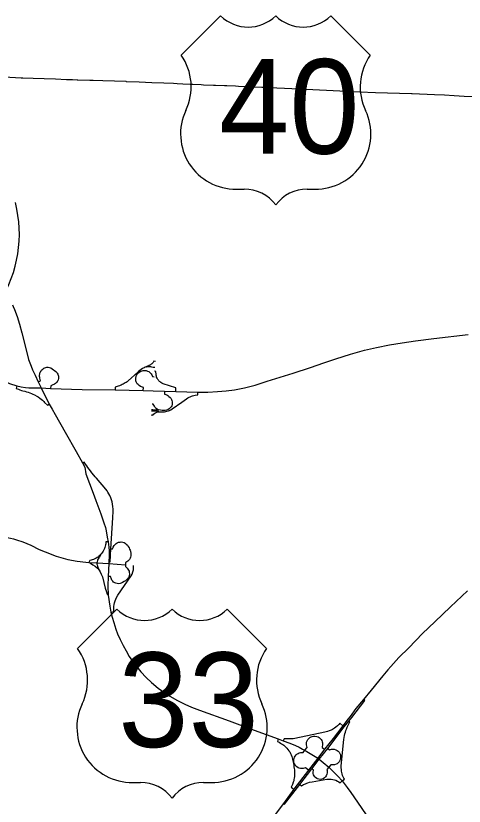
# Model space of a CAD drawing. Extents: x -7.1 to 34, y 0 to 22.
# Drawn here: x 6.584 to 7.196, y 16.034 to 17.111 of the extents above; entities that cross this region are included whole.
import ezdxf

# ---------------------------------------------------------------- set-up
doc = ezdxf.new("R2010")
doc.units = 0
for name, color, linetype in [('GM_X_Interchange_Ramps', 7, 'Continuous'), ('GM_X_Interstate_Route', 7, 'Continuous'), ('GM_X_Interstate_Shield', 7, 'Continuous'), ('GM_X_State_Route', 7, 'Continuous'), ('GM_X_US_Route', 7, 'Continuous'), ('GM_X_US_Shield', 7, 'Continuous')]:
    doc.layers.add(name, color=color, linetype=linetype)

msp = doc.modelspace()

# ---------------------------------------------------------------- linework, layer by layer
at = {"layer": 'GM_X_Interchange_Ramps'}
for points in [[(6.7745, 16.6397), (6.7724, 16.6399), (6.7713, 16.6384), (6.7705, 16.6375), (6.7696, 16.6366), (6.7689, 16.636), (6.768, 16.6353), (6.7669, 16.6346), (6.7659, 16.6341), (6.7647, 16.6335), (6.7637, 16.6332), (6.762, 16.6325), (6.7605, 16.6319), (6.759, 16.6311), (6.757, 16.63), (6.755, 16.6288), (6.7532, 16.6275), (6.7514, 16.626), (6.7504, 16.6253), (6.7372, 16.6131), (6.7358, 16.6121), (6.7345, 16.6112), (6.7333, 16.6104), (6.7319, 16.6095), (6.7303, 16.6087), (6.7291, 16.6081), (6.7279, 16.6076), (6.7263, 16.607), (6.7253, 16.6066), (6.7237, 16.6062), (6.7197, 16.6048), (6.7196, 16.6009)], [(6.6146, 16.612), (6.6178, 16.6134), (6.6169, 16.617), (6.6167, 16.618), (6.6165, 16.6193), (6.6165, 16.6202), (6.6165, 16.6213), (6.6167, 16.6225), (6.617, 16.6237), (6.6175, 16.625), (6.6181, 16.6261), (6.6188, 16.6272), (6.6198, 16.6284), (6.6211, 16.6294), (6.6225, 16.6304), (6.6237, 16.6309), (6.625, 16.6314), (6.6265, 16.6317), (6.6282, 16.6317), (6.63, 16.6316), (6.6318, 16.6311), (6.6338, 16.6295), (6.6389, 16.6259), (6.64, 16.6247), (6.6406, 16.6239), (6.6414, 16.6223), (6.6418, 16.6212), (6.6422, 16.6195), (6.6423, 16.6181), (6.6422, 16.6166), (6.6418, 16.6148), (6.6412, 16.6134), (6.6407, 16.6123), (6.6399, 16.6112), (6.6392, 16.6105), (6.6383, 16.6097), (6.637, 16.6088), (6.636, 16.6082), (6.6346, 16.6077), (6.6318, 16.6067), (6.6313, 16.6027)], [(6.758, 16.5999), (6.7581, 16.6042), (6.7556, 16.6051), (6.7541, 16.6058), (6.7522, 16.6069), (6.7508, 16.6081), (6.7497, 16.6094), (6.7489, 16.6109), (6.7484, 16.6121), (6.748, 16.6135), (6.7478, 16.6148), (6.7478, 16.6169), (6.7482, 16.6192), (6.7489, 16.6208), (6.7497, 16.6223), (6.7505, 16.6233), (6.7519, 16.6248), (6.7532, 16.6257), (6.7547, 16.6265), (6.7563, 16.6271), (6.7576, 16.6274), (6.7587, 16.6275), (6.7601, 16.6275), (6.762, 16.6273), (6.7639, 16.6266), (6.7653, 16.6259), (6.7666, 16.625), (6.768, 16.6238), (6.7688, 16.6228), (6.7695, 16.6216), (6.7707, 16.6191), (6.7727, 16.6189)], [(6.7738, 16.6314), (6.7715, 16.6316), (6.7697, 16.632), (6.7681, 16.6323), (6.7668, 16.6324), (6.7656, 16.6324), (6.7645, 16.6324), (6.7632, 16.6323), (6.7622, 16.6321), (6.762, 16.6325)], [(6.8022, 16.5986), (6.8023, 16.6039), (6.785, 16.6092), (6.7842, 16.6097), (6.7832, 16.6102), (6.7819, 16.611), (6.7808, 16.6118), (6.78, 16.6126), (6.7792, 16.6134), (6.7785, 16.6143), (6.7779, 16.6151), (6.7773, 16.6161), (6.7768, 16.6171), (6.7762, 16.6185), (6.7758, 16.6198), (6.7755, 16.621), (6.7754, 16.6219), (6.775, 16.6261), (6.7733, 16.6263)], [(6.5854, 16.6065), (6.5845, 16.603), (6.5877, 16.6018), (6.5897, 16.601), (6.5917, 16.6003), (6.5936, 16.5998), (6.5964, 16.5991), (6.5985, 16.5985), (6.6009, 16.5978), (6.6031, 16.597), (6.6056, 16.596), (6.6074, 16.5952), (6.6096, 16.5941), (6.6126, 16.5925), (6.6146, 16.5913), (6.6168, 16.5898), (6.6188, 16.5885), (6.6206, 16.5869), (6.6223, 16.5852), (6.6234, 16.5838), (6.6271, 16.5802), (6.6297, 16.5817)], [(6.7687, 16.5668), (6.771, 16.5665), (6.7721, 16.5678), (6.7738, 16.5692), (6.7747, 16.5698), (6.7765, 16.5706), (6.7778, 16.5709), (6.7784, 16.571), (6.7798, 16.5711), (6.7852, 16.5709), (6.7871, 16.5712), (6.7889, 16.5715), (6.7902, 16.5718), (6.7922, 16.5725), (6.7936, 16.573), (6.7955, 16.5739), (6.7973, 16.575), (6.8105, 16.5844), (6.8169, 16.5887), (6.8187, 16.5899), (6.8206, 16.5909), (6.8221, 16.5916), (6.8236, 16.5922), (6.8253, 16.5928), (6.827, 16.5933), (6.8285, 16.5936), (6.8325, 16.5943), (6.8325, 16.598)], [(6.787, 16.5991), (6.7869, 16.5951), (6.7886, 16.5945), (6.79, 16.594), (6.7914, 16.5932), (6.7929, 16.5921), (6.7944, 16.5906), (6.7954, 16.5895), (6.7965, 16.5879), (6.7971, 16.5866), (6.7975, 16.5848), (6.7975, 16.5825), (6.7973, 16.581), (6.7967, 16.5793), (6.7958, 16.5777), (6.7947, 16.5763), (6.7933, 16.575), (6.7914, 16.5739), (6.7896, 16.5733), (6.7879, 16.573), (6.7858, 16.5728), (6.7837, 16.5729), (6.7814, 16.5732), (6.7789, 16.5738), (6.7774, 16.5744), (6.7755, 16.5757), (6.7743, 16.577), (6.7731, 16.5786), (6.7723, 16.58), (6.7716, 16.5816), (6.7701, 16.5817)], [(6.7692, 16.5724), (6.7707, 16.5725), (6.7783, 16.5722), (6.7784, 16.571)], [(6.7774, 16.5744), (6.777, 16.5734), (6.7709, 16.5737), (6.7693, 16.5739)], [(6.7111, 16.3667), (6.7127, 16.3667), (6.7137, 16.3842), (6.7163, 16.4266), (6.7168, 16.4357), (6.7168, 16.4386), (6.7166, 16.4419), (6.7161, 16.445), (6.7154, 16.4484), (6.7146, 16.4509), (6.7137, 16.4537), (6.7123, 16.4569), (6.7109, 16.4594), (6.7097, 16.4616), (6.7085, 16.4634), (6.7067, 16.4657), (6.6941, 16.4808), (6.6925, 16.4826), (6.6905, 16.4849), (6.688, 16.4879), (6.6859, 16.4905), (6.6842, 16.4927), (6.6824, 16.4951), (6.6808, 16.4974), (6.6792, 16.4996), (6.6773, 16.5025), (6.6751, 16.5014)], [(6.7099, 16.394), (6.707, 16.3937), (6.7068, 16.3913), (6.7064, 16.3897), (6.706, 16.3878), (6.7056, 16.3863), (6.705, 16.3848), (6.7041, 16.3828), (6.7033, 16.3812), (6.7024, 16.3799), (6.7013, 16.3783), (6.7002, 16.3769), (6.699, 16.3757), (6.698, 16.3746), (6.6967, 16.3735), (6.6951, 16.3724), (6.6938, 16.3716), (6.692, 16.3707), (6.6901, 16.37), (6.685, 16.3686), (6.6837, 16.3658)], [(6.7137, 16.3842), (6.7161, 16.3841), (6.7168, 16.3865), (6.7183, 16.3888), (6.7194, 16.3902), (6.7209, 16.3915), (6.7224, 16.3925), (6.7243, 16.3932), (6.7262, 16.3936), (6.728, 16.3937), (6.7302, 16.3934), (6.7318, 16.3928), (6.7333, 16.3921), (6.7348, 16.3909), (6.7362, 16.3895), (6.7374, 16.3877), (6.7385, 16.3857), (6.7393, 16.384), (6.7399, 16.3824), (6.7403, 16.381), (6.7408, 16.3781), (6.7408, 16.3748), (6.7406, 16.3731), (6.74, 16.3714), (6.7391, 16.3698), (6.7379, 16.3683), (6.7368, 16.3673), (6.7353, 16.3664), (6.7339, 16.3658), (6.7337, 16.3624)], [(6.699, 16.3757), (6.6996, 16.3751), (6.6988, 16.3742), (6.6979, 16.3731), (6.6973, 16.3722), (6.6964, 16.3708), (6.6957, 16.3694), (6.6953, 16.3684), (6.6949, 16.3666), (6.6948, 16.3651)], [(6.6948, 16.3651), (6.6947, 16.3636), (6.695, 16.3623), (6.6953, 16.3609), (6.6957, 16.3597), (6.6962, 16.3585), (6.6968, 16.3573), (6.6974, 16.3564), (6.6979, 16.3556), (6.6976, 16.3553)], [(6.7337, 16.3624), (6.7336, 16.3601), (6.7349, 16.3591), (6.7361, 16.358), (6.7371, 16.3568), (6.738, 16.3553), (6.7385, 16.3538), (6.7389, 16.3522), (6.739, 16.3504), (6.7385, 16.3469), (6.7377, 16.3451), (6.737, 16.3439), (6.7357, 16.3425), (6.7337, 16.3406), (6.7321, 16.3396), (6.7298, 16.3384), (6.7279, 16.3377), (6.7265, 16.3372), (6.724, 16.3368), (6.7223, 16.337), (6.7205, 16.3374), (6.7191, 16.338), (6.7175, 16.339), (6.7163, 16.3402), (6.7152, 16.3415), (6.7144, 16.3429), (6.7131, 16.3464), (6.7099, 16.3465)], [(6.7136, 16.298), (6.7177, 16.2987), (6.7177, 16.3026), (6.7178, 16.3055), (6.7183, 16.3083), (6.7187, 16.3105), (6.7196, 16.3133), (6.7204, 16.3156), (6.7215, 16.3179), (6.7233, 16.3211), (6.7415, 16.3473), (6.7427, 16.3498), (6.7437, 16.3528), (6.7444, 16.3559), (6.7446, 16.3583), (6.7447, 16.3598), (6.7447, 16.3616)], [(6.9491, 16.0374), (6.9507, 16.0362), (6.9716, 16.0632), (6.9879, 16.0844), (6.998, 16.0975), (7.0095, 16.1123), (7.0321, 16.1415), (7.0383, 16.1494), (7.0423, 16.1545), (7.0603, 16.1774), (7.0581, 16.1791)], [(7.0294, 16.0679), (7.0322, 16.0703), (7.0315, 16.0716), (7.0305, 16.0736), (7.0298, 16.0756), (7.0292, 16.0775), (7.0287, 16.0794), (7.0283, 16.0815), (7.0281, 16.0834), (7.0279, 16.0858), (7.028, 16.0886), (7.0317, 16.1245), (7.032, 16.1271), (7.0325, 16.1299), (7.033, 16.1322), (7.0336, 16.1345), (7.0342, 16.1365), (7.035, 16.1385), (7.036, 16.1411), (7.0369, 16.143), (7.0387, 16.1467), (7.0396, 16.1484), (7.0383, 16.1494)], [(7.0301, 16.1433), (7.026, 16.1465), (7.0245, 16.1448), (7.0228, 16.1432), (7.0207, 16.1414), (7.0186, 16.1399), (7.016, 16.1383), (7.014, 16.1373), (7.0114, 16.1362), (7.009, 16.1353), (7.0056, 16.1344), (6.9647, 16.1257), (6.9623, 16.1254), (6.9595, 16.1252), (6.9538, 16.1252), (6.9499, 16.1252), (6.9489, 16.1225)], [(6.9782, 16.1099), (6.9814, 16.1135), (6.9808, 16.1155), (6.9805, 16.1172), (6.9804, 16.119), (6.9807, 16.1208), (6.9814, 16.1228), (6.9823, 16.1243), (6.9837, 16.126), (6.9851, 16.1272), (6.9867, 16.1281), (6.9882, 16.1287), (6.9899, 16.1291), (6.9921, 16.1292), (6.9947, 16.1287), (6.9963, 16.1281), (6.9979, 16.1271), (6.9994, 16.1258), (7.0005, 16.1246), (7.0013, 16.1232), (7.002, 16.1214), (7.0024, 16.1198), (7.0025, 16.118), (7.0021, 16.1137), (7.0052, 16.1112)], [(6.9421, 16.1252), (6.9408, 16.1219), (6.9433, 16.1206), (6.9449, 16.1196), (6.9465, 16.1187), (6.9482, 16.1176), (6.9498, 16.1165), (6.9512, 16.1153), (6.9525, 16.1141), (6.9539, 16.1126), (6.9553, 16.1109), (6.9566, 16.1091), (6.9576, 16.1075), (6.9587, 16.1055), (6.9596, 16.1036), (6.9605, 16.1013), (6.961, 16.0996), (6.9616, 16.0975), (6.962, 16.0954), (6.9624, 16.0936), (6.9627, 16.0916), (6.9631, 16.0892), (6.9634, 16.0872), (6.9637, 16.0849), (6.964, 16.083), (6.9642, 16.0813), (6.9643, 16.0794), (6.9644, 16.0776), (6.9644, 16.076), (6.9642, 16.0738), (6.9639, 16.0718), (6.9635, 16.0699), (6.9631, 16.0681), (6.9625, 16.0661), (6.9613, 16.0629), (6.9597, 16.0593), (6.9632, 16.0567)], [(6.9832, 16.0827), (6.9792, 16.0857), (6.9759, 16.0849), (6.9743, 16.0847), (6.9726, 16.0849), (6.9707, 16.0853), (6.969, 16.086), (6.9673, 16.0872), (6.9661, 16.0883), (6.9649, 16.0898), (6.9641, 16.0914), (6.9635, 16.093), (6.9632, 16.0949), (6.9632, 16.0969), (6.9636, 16.0987), (6.9642, 16.1004), (6.9651, 16.1019), (6.9663, 16.1034), (6.9675, 16.1046), (6.969, 16.1055), (6.9706, 16.1062), (6.9726, 16.1067), (6.976, 16.1069), (6.9782, 16.1099)], [(7.0095, 16.1123), (7.0117, 16.1105), (7.0147, 16.1113), (7.0164, 16.1114), (7.0182, 16.1112), (7.0205, 16.1105), (7.0226, 16.1094), (7.0238, 16.1084), (7.0249, 16.1072), (7.026, 16.1055), (7.0268, 16.1034), (7.0271, 16.1012), (7.0271, 16.0993), (7.0267, 16.0975), (7.0261, 16.0958), (7.0251, 16.0941), (7.024, 16.0929), (7.0224, 16.0915), (7.0208, 16.0907), (7.0188, 16.09), (7.0169, 16.0897), (7.0139, 16.0897), (7.0112, 16.0866)], [(7.0112, 16.0866), (7.0085, 16.0836), (7.0087, 16.0821), (7.0088, 16.0806), (7.0087, 16.079), (7.0084, 16.077), (7.0074, 16.0748), (7.0064, 16.0734), (7.005, 16.0721), (7.0032, 16.071), (7.0016, 16.0704), (6.9997, 16.0701), (6.9976, 16.0702), (6.9957, 16.0707), (6.9945, 16.0713), (6.9929, 16.0725), (6.9917, 16.0737), (6.9908, 16.0751), (6.9902, 16.0765), (6.9898, 16.0782), (6.9896, 16.0798), (6.9899, 16.0828), (6.9879, 16.0844)], [(6.9716, 16.0632), (6.9739, 16.0615), (6.9765, 16.0629), (6.9779, 16.0636), (6.9792, 16.0642), (6.9808, 16.0649), (6.9823, 16.0654), (6.9846, 16.0661), (6.9882, 16.0669), (7.0084, 16.0702), (7.0105, 16.0705), (7.0126, 16.0705), (7.0144, 16.0704), (7.0164, 16.0701), (7.0187, 16.0696), (7.0204, 16.069), (7.023, 16.0677), (7.0246, 16.0667), (7.0264, 16.0654), (7.0294, 16.0679)]]:
    msp.add_lwpolyline(points, dxfattribs=at)
at = {"layer": 'GM_X_Interstate_Route'}
for points in [[(6.6188, 16.6036), (6.6313, 16.6027), (6.6747, 16.6015), (6.7196, 16.6009), (6.758, 16.5999), (6.7716, 16.5995), (6.787, 16.5991), (6.8022, 16.5986), (6.8325, 16.598), (6.8458, 16.5979), (6.8593, 16.5986), (6.8711, 16.5996), (6.8824, 16.6012), (6.8961, 16.6039), (6.9106, 16.6075), (6.9268, 16.6127), (6.9625, 16.6239), (6.9858, 16.6315), (7.004, 16.638), (7.0205, 16.6431), (7.0404, 16.6495), (7.0597, 16.655), (7.0759, 16.6587), (7.0938, 16.6624), (7.111, 16.6653), (7.1294, 16.668), (7.154, 16.671), (7.2009, 16.6766)], [(6.5633, 16.6172), (6.5686, 16.6133), (6.5755, 16.6097), (6.5854, 16.6065)], [(6.5854, 16.6065), (6.5914, 16.6049), (6.5975, 16.604), (6.6019, 16.6039), (6.6188, 16.6036)], [(7.2001, 16.3272), (7.177, 16.3054), (7.1556, 16.2849), (7.1388, 16.269), (7.1201, 16.2493), (7.1066, 16.236), (7.0954, 16.2239), (7.0917, 16.2195)], [(7.0917, 16.2195), (7.0846, 16.2112), (7.0687, 16.1917), (7.0581, 16.1791)], [(7.0581, 16.1791), (7.048, 16.1666), (7.04, 16.156), (7.0372, 16.1524)], [(7.0372, 16.1524), (7.0301, 16.1433), (7.0169, 16.1259), (7.0052, 16.1112), (6.9961, 16.0989)], [(6.9961, 16.0989), (6.9832, 16.0827), (6.9632, 16.0567), (6.9491, 16.0374)], [(6.9491, 16.0374), (6.938, 16.0223), (6.9058, 15.9807), (6.88, 15.9462), (6.8459, 15.9025), (6.8229, 15.8718)]]:
    msp.add_lwpolyline(points, dxfattribs=at)
at = {"layer": 'GM_X_Interstate_Shield'}
msp.add_arc((6.4154, 16.8136), 0.1735, 281.537, 14.1934, dxfattribs=at)
at = {"layer": 'GM_X_State_Route'}
for points in [[(6.5356, 16.4017), (6.543, 16.4023), (6.5493, 16.4026), (6.5551, 16.4022), (6.5607, 16.4018), (6.5681, 16.4006), (6.577, 16.3989), (6.581, 16.3978), (6.5852, 16.3965), (6.5935, 16.3937), (6.6044, 16.3893), (6.6159, 16.3836), (6.6241, 16.3802), (6.6393, 16.3744), (6.6552, 16.3697), (6.6676, 16.3675), (6.6795, 16.3662), (6.6837, 16.3658), (6.6841, 16.3656)], [(6.6837, 16.3658), (6.6948, 16.3651), (6.7109, 16.3642), (6.7337, 16.3624)], [(6.6841, 16.3656), (6.686, 16.3646), (6.6891, 16.3627), (6.6924, 16.3605), (6.6953, 16.3579), (6.6976, 16.3553), (6.6992, 16.3528), (6.7007, 16.3499), (6.7021, 16.3462), (6.7061, 16.3308), (6.7076, 16.3258), (6.7088, 16.3227), (6.7102, 16.3211)]]:
    msp.add_lwpolyline(points, dxfattribs=at)
at = {"layer": 'GM_X_US_Route'}
for points in [[(6.4832, 17.0306), (6.5095, 17.0297), (6.5145, 17.0295), (6.538, 17.0291), (6.5444, 17.0284), (6.5449, 17.0284), (6.5607, 17.0277), (6.5655, 17.0275), (6.5758, 17.027), (6.5915, 17.0264), (6.5938, 17.0263), (6.6077, 17.0257), (6.6079, 17.0257), (6.6229, 17.0252), (6.638, 17.0247), (6.6532, 17.0242), (6.6608, 17.024)], [(6.6608, 17.024), (6.6616, 17.0239), (6.6679, 17.0237), (6.6686, 17.0237), (6.6849, 17.0232), (6.6896, 17.023), (6.7029, 17.0226), (6.7189, 17.0221), (6.7343, 17.0216), (6.7348, 17.0215), (6.7525, 17.0208), (6.7694, 17.0201), (6.7859, 17.0194), (6.7991, 17.0188), (6.8041, 17.0186), (6.8121, 17.0182), (6.8218, 17.0178), (6.8256, 17.0176), (6.8371, 17.0171), (6.8402, 17.0169), (6.8536, 17.0164), (6.8565, 17.0163), (6.8687, 17.0158), (6.8717, 17.0156), (6.8836, 17.0152), (6.8879, 17.015), (6.8965, 17.0146), (6.9089, 17.0139), (6.9197, 17.0136), (6.9209, 17.0136)], [(6.9209, 17.0136), (6.9299, 17.0132), (6.9604, 17.0118), (6.9694, 17.0112), (6.9704, 17.0111), (7.0168, 17.0089), (7.0532, 17.0072), (7.0535, 17.0072), (7.0746, 17.0065), (7.1238, 17.0049), (7.1246, 17.0048), (7.1552, 17.0034), (7.1689, 17.0029), (7.1821, 17.0023), (7.1958, 17.0013), (7.2079, 17.0007), (7.2084, 17.0007), (7.2239, 17), (7.2302, 16.9997), (7.2536, 16.9986), (7.2543, 16.9986), (7.2786, 16.9976)], [(6.5795, 16.717), (6.5805, 16.7148), (6.5824, 16.7103), (6.586, 16.7011), (6.5891, 16.6907), (6.5923, 16.6789), (6.5989, 16.652), (6.6016, 16.6424), (6.605, 16.6332), (6.607, 16.6283), (6.6105, 16.6211), (6.6146, 16.612), (6.6188, 16.6036)], [(6.6188, 16.6036), (6.6297, 16.5817), (6.6337, 16.5746)], [(6.6337, 16.5746), (6.6377, 16.5675)], [(6.6377, 16.5675), (6.6512, 16.5435), (6.6663, 16.517), (6.6751, 16.5014), (6.6782, 16.4956), (6.6798, 16.4867), (6.6896, 16.4601), (6.6931, 16.4502), (6.7001, 16.4318), (6.7042, 16.4196), (6.7062, 16.4135), (6.7072, 16.409), (6.7088, 16.4), (6.7099, 16.394), (6.7108, 16.3865), (6.7112, 16.3815), (6.7112, 16.3747), (6.7111, 16.3667)], [(6.7111, 16.3667), (6.7109, 16.3642), (6.7099, 16.3465), (6.7098, 16.3337), (6.7102, 16.3211)], [(6.7102, 16.3211), (6.7121, 16.3064), (6.7136, 16.298), (6.7153, 16.2913), (6.7176, 16.2838), (6.7206, 16.2749), (6.7228, 16.2685), (6.7262, 16.2609), (6.7304, 16.2524), (6.7344, 16.2452), (6.7389, 16.2377), (6.7457, 16.2281), (6.7548, 16.2168), (6.7621, 16.209), (6.7692, 16.2022), (6.7782, 16.1946), (6.792, 16.1847), (6.8035, 16.178), (6.8146, 16.1724), (6.8236, 16.1686), (6.8347, 16.1644), (6.8749, 16.1497), (6.9094, 16.1371), (6.9421, 16.1252), (6.9489, 16.1225), (6.9515, 16.1217), (6.9603, 16.1184), (6.9654, 16.1163), (6.9705, 16.1138), (6.9751, 16.1115), (6.9782, 16.1099), (6.981, 16.1082), (6.9877, 16.1042), (6.9922, 16.1014)], [(6.9922, 16.1014), (6.9961, 16.0989), (6.998, 16.0975), (7.0035, 16.093), (7.0112, 16.0866), (7.0176, 16.0805), (7.0234, 16.0744), (7.0294, 16.0679), (7.036, 16.0592), (7.0412, 16.0522), (7.055, 16.0319), (7.0705, 16.009), (7.0852, 15.9878), (7.0942, 15.9766), (7.1036, 15.9656), (7.1117, 15.957), (7.122, 15.9472), (7.1594, 15.9152), (7.1612, 15.9136), (7.1858, 15.8925), (7.1941, 15.8853)]]:
    msp.add_lwpolyline(points, dxfattribs=at)
at = {"layer": 'GM_X_US_Shield'}
for p, q in [((6.8634, 17.1108), (6.8097, 17.0571)), ((7.0674, 17.0571), (7.0137, 17.1108)), ((6.8849, 16.8746), (6.8956, 16.8746)), ((6.9815, 16.8746), (6.9922, 16.8746)), ((6.722, 16.3021), (6.6683, 16.2484)), ((6.926, 16.2484), (6.8723, 16.3021)), ((6.7435, 16.0658), (6.7542, 16.0658)), ((6.8401, 16.0658), (6.8509, 16.0658))]:
    msp.add_line(p, q, dxfattribs=at)
for centre, radius, start, end in [((6.901, 17.1492), 0.0537, 225.573, 314.427), ((6.9761, 17.1492), 0.0537, 225.573, 314.427), ((6.7481, 17.014), 0.0752, 334.5471, 35.0009), ((7.129, 17.014), 0.0752, 144.9991, 205.4529), ((6.884, 16.9497), 0.0752, 154.8319, 270.6383), ((6.9931, 16.9497), 0.0752, 269.3617, 25.1681), ((6.8956, 16.8209), 0.0537, 36.8699, 90), ((6.9815, 16.8209), 0.0537, 90, 143.1301), ((6.7596, 16.3404), 0.0537, 225.573, 314.427), ((6.8348, 16.3404), 0.0537, 225.573, 314.427), ((6.6068, 16.2053), 0.0752, 334.5471, 35.0009), ((6.9876, 16.2053), 0.0752, 144.9991, 205.4529), ((6.7426, 16.141), 0.0752, 154.8319, 270.6383), ((6.8517, 16.141), 0.0752, 269.3617, 25.1681), ((6.7542, 16.0122), 0.0537, 36.8699, 90), ((6.8401, 16.0122), 0.0537, 90, 143.1301)]:
    msp.add_arc(centre, radius, start, end, dxfattribs=at)

# ---------------------------------------------------------------- texts
for s, p in [('40', (6.8612, 16.9229)), ('33', (6.7238, 16.1142))]:
    msp.add_text(s, height=0.12885, dxfattribs=at).set_placement(p)

doc.saveas('drawing.dxf')
